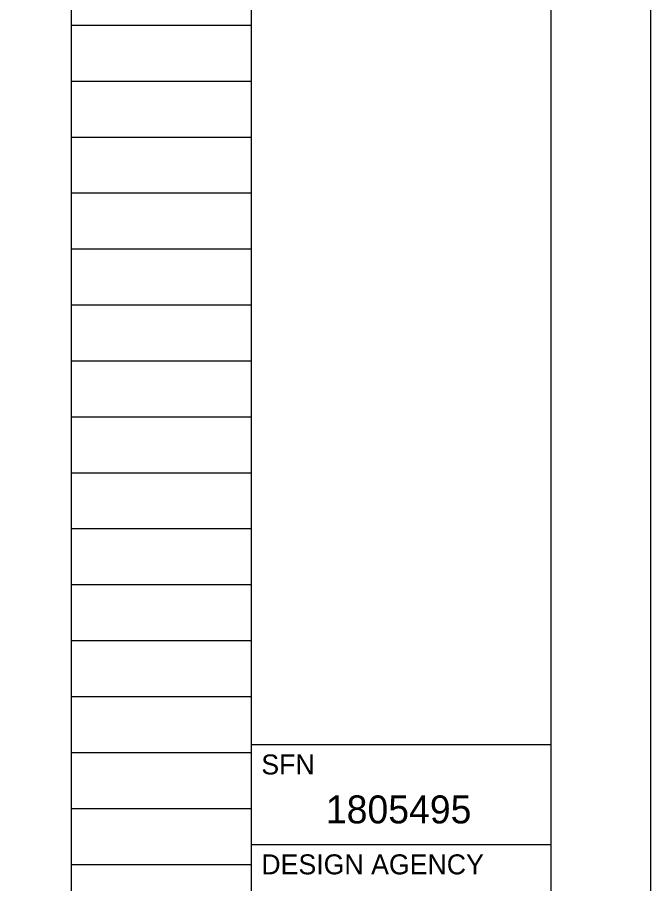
# Model space of a CAD drawing. Extents: x 0 to 34, y 0 to 22.
# Drawn here: x 30.828 to 34, y 4.803 to 9.139 of the extents above; entities that cross this region are included whole.
import ezdxf

# ---------------------------------------------------------------- set-up
doc = ezdxf.new("R2010")
doc.units = 0
for name, color, linetype in [('SH_Border', 7, 'Continuous'), ('SH_Cut_Line', 7, 'Continuous'), ('SH_Data', 7, 'Continuous')]:
    doc.layers.add(name, color=color, linetype=linetype)

msp = doc.modelspace()

# ---------------------------------------------------------------- linework, layer by layer
at = {"layer": 'SH_Border'}
for p, q in [((32, 0.5), (32, 21.5)), ((32, 5.5), (33.5, 5.5)), ((32, 5), (33.5, 5))]:
    msp.add_line(p, q, dxfattribs=at)
msp.add_lwpolyline([(1.5, 21.5), (33.5, 21.5), (33.5, 0.5), (1.5, 0.5)], close=True, dxfattribs=at)
at = {"layer": 'SH_Cut_Line'}
msp.add_lwpolyline([(0, 0), (34, 0), (34, 22), (0, 22)], close=True, dxfattribs=at)
at = {"layer": 'SH_Data'}
for p, q in [((31.1, 0.98), (31.1, 21.14)), ((31.1, 0.98), (31.1, 21.14)), ((32, 0.98), (32, 21.14)), ((32, 0.98), (32, 21.14)), ((31.1, 9.1), (32, 9.1)), ((31.1, 9.1), (32, 9.1)), ((31.1, 8.82), (32, 8.82)), ((31.1, 8.82), (32, 8.82)), ((31.1, 8.54), (32, 8.54)), ((31.1, 8.54), (32, 8.54)), ((31.1, 8.26), (32, 8.26)), ((31.1, 8.26), (32, 8.26)), ((31.1, 7.98), (32, 7.98)), ((31.1, 7.98), (32, 7.98)), ((31.1, 7.7), (32, 7.7)), ((31.1, 7.7), (32, 7.7)), ((31.1, 7.42), (32, 7.42)), ((31.1, 7.42), (32, 7.42)), ((31.1, 7.14), (32, 7.14)), ((31.1, 7.14), (32, 7.14)), ((31.1, 6.86), (32, 6.86)), ((31.1, 6.86), (32, 6.86)), ((31.1, 6.58), (32, 6.58)), ((31.1, 6.58), (32, 6.58)), ((31.1, 6.3), (32, 6.3)), ((31.1, 6.3), (32, 6.3)), ((31.1, 6.02), (32, 6.02)), ((31.1, 6.02), (32, 6.02)), ((31.1, 5.74), (32, 5.74)), ((31.1, 5.74), (32, 5.74)), ((31.1, 5.46), (32, 5.46)), ((31.1, 5.46), (32, 5.46)), ((31.1, 5.18), (32, 5.18)), ((31.1, 5.18), (32, 5.18)), ((31.1, 4.9), (32, 4.9)), ((31.1, 4.9), (32, 4.9))]:
    msp.add_line(p, q, dxfattribs=at)

# ---------------------------------------------------------------- texts
for s, height, p in [('SFN', 0.1, (32.05, 5.35)), ('1805495', 0.14, (32.3733, 5.105)), ('DESIGN AGENCY', 0.1, (32.05, 4.85))]:
    msp.add_text(s, height=height, dxfattribs=at).set_placement(p)

doc.saveas('drawing.dxf')
